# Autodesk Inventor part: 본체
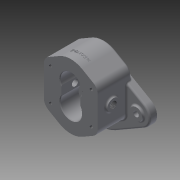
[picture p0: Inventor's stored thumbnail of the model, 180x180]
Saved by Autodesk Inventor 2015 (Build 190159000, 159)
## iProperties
Created: 2025-11
Part Number: 본체
Material: 일반
Document SubType Name: Modeling
Designer: user
Density: 1 g/cm^3
Appearance: 기본값
Author: user
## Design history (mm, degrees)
sketch "스케치1"
  geometry: L1 (74, 17.321)-(26, 45.033); L2 (-74, 17.321)-(-26, 45.033); L3 (74, -17.321)-(26, -45.033); L4 (-26, -45.033)-(-74, -17.321); A1 r 52 centre (0, 0) between (26, 45.033) and (-26, 45.033); A2 r 20 centre (-64, 0) between (-74, -17.321) and (-74, 17.321); A3 r 20 centre (64, 0) between (74, 17.321) and (74, -17.321); 1 further point
  constraints: 8 end point, 8 point on circle, 8 tangent, 3 centre point, 2 horizontal alignment, 1 coincident
  dimensions: "d0" = 104 diameter of A1; "d1" = 40 diameter of A2; "d2" = 40 diameter of A3; "d3" = 64 distance of A2.centre point (0, 0); "d4" = 64 distance of A3.centre point (0, 0)
extrude "돌출1" new body sketch "스케치1" distance "d5" = 12; taper "d6" = 0 deg
sketch "스케치2"
  geometry: L1 (-97.916, 16)-(97.916, 16); L2 (-19, 64.909)-(-45, 49.898); L3 (-45, 49.898)-(-45, -17.898); L4 (-45, -17.898)-(-19, -32.909); L5 (0, 0)-(0, 32); L6 (19, 64.909)-(45, 49.898); L7 (45, 49.898)-(45, -17.898); L8 (45, -17.898)-(19, -32.909); A1 r 52 centre (0, 0) between (-26, -45.033) and (26, -45.033) reference; A2 r 52 centre (0, 0) between (26, 45.033) and (-26, 45.033) reference; A3 r 38 centre (0, 0) between (-19, -32.909) and (19, -32.909); A4 r 38 centre (0, 32) between (-19, 64.909) and (19, 64.909); 1 further point
  constraints: 16 end point, 4 point on circle, 2 centre point, 2 tangent, 2 vertical, 2 vertical alignment, 1 coincident, 1 horizontal, 1 midpoint, 1 parallel, 2 other
  dimensions: "d7" = 76 diameter of A3; "d8" = 16 distance from line of L1 A1.centre; "d9" = 76 diameter of A4; "d10" = 16 distance from line of L1 L5.end; "d11" = 60 deg angle of L4 L2; "d12" = 60 deg angle of L8 L6; "d13" = 45 distance from line of A1.centre L3; "d14" = 90 distance between parallel lines of L3 L7; "d88" = 195.83139 distance of L1.start L1.end
extrude "돌출2" join sketch "스케치2" distance "d15" = 48; taper "d17" = 0 deg; dims "d16" = 8, "d18" = 0
sketch "스케치3"
  geometry: L1 (-16, 0)-(16, 0); L2 (16, 0)-(16, 32); L3 (16, 32)-(-16, 32); L4 (-16, 32)-(-16, 0); C1 r 18 at (0, 32); C2 r 18 at (0, 0); A1 r 38 centre (0, 32) between (19, 64.909) and (-19, 64.909) reference; A2 r 38 centre (0, 0) between (-19, -32.909) and (19, -32.909) reference
  constraints: 8 end point, 2 centre point, 2 coincident, 2 midpoint, 2 parallel, 1 horizontal, 1 perpendicular
  dimensions: "d19" = 36 diameter of C1; "d20" = 36 diameter of C2; "d21" = 16 distance from line of A2.centre L4; "d22" = 32 distance between parallel lines of L2 L4
extrude "돌출3" cut sketch "스케치3" distance "d23" = 31; taper "d24" = 0 deg
sketch "스케치4"
  geometry: L1 (0, 0)-(51.962, 0) reference; L2 (51.962, -48)-(-15.834, -48) reference; L3 (25.817, -48)-(10.31, -48) reference; L4 (18.064, -48)-(18.064, 0); C1 r 10 at (18.064, -25); 1 further point
  constraints: 2 end point, 2 point on line, 1 centre point, 1 midpoint, 1 perpendicular
  dimensions: "d25" = 20 diameter of C1; "d26" = 23 distance from line of L2 C1.centre
extrude "돌출4" join sketch "스케치4" distance "d27" = 3; taper "d28" = 0 deg
sketch "스케치5"
  geometry: C1 r 10 at (0, 0) reference; 1 further point
hole "구멍1" sketch "스케치5" at (0, 0) diameter "d29" = 10.5; stored, may be unused: countersink angle "d35" = 90 deg, drill point angle "d37" = 118 deg; dims "d30" = 11, "d31" = 0.62479, "d32" = 10.589, "d33" = 4, "d34" = 2, "d36" = 17.5
sketch "스케치6"
  geometry: L1 (16, 8.246)-(16, 23.754) reference; L2 (-16, 23.754)-(-16, 8.246) reference; L3 (19, 64.909)-(45, 49.898) reference; L4 (45, 49.898)-(45, 22) reference; L5 (45, 22)-(48, 22) reference; L6 (48, 22)-(48, 10) reference; L7 (48, 10)-(45, 10) reference; L8 (45, 10)-(45, -17.898) reference; L9 (45, -17.898)-(19, -32.909) reference; L10 (-19, -32.909)-(-45, -17.898) reference; L11 (-45, -17.898)-(-45, 10) reference; L12 (-45, 10)-(-48, 10) reference; L13 (-48, 10)-(-48, 22) reference; L14 (-48, 22)-(-45, 22) reference; L15 (-45, 22)-(-45, 49.898) reference; L16 (-45, 49.898)-(-19, 64.909) reference; L17 (-48, 16)-(48, 16); C1 r 11.5 at (0, 32); C2 r 11.5 at (0, 0); A1 r 18 centre (0, 32) between (16, 23.754) and (-16, 23.754) reference; A2 r 18 centre (0, 32) between (16, 23.754) and (-16, 23.754) reference; A3 r 18 centre (0, 0) between (-16, 8.246) and (16, 8.246) reference; A4 r 38 centre (0, 32) between (19, 64.909) and (-19, 64.909) reference; A5 r 38 centre (0, 0) between (-19, -32.909) and (19, -32.909) reference
  constraints: 2 centre point, 2 end point, 2 midpoint, 1 coincident, 1 vertical alignment
  dimensions: "d38" = 23 diameter of C1; "d39" = 23 diameter of C2; "d40" = 16 distance from line of C2.centre L17
extrude "돌출5" cut sketch "스케치6" distance "d41" = 15; taper "d42" = 0 deg
sketch "스케치7"
  geometry: C1 r 25 at (0, 0); A1 r 18 centre (0, 0) between (16, -8.246) and (-16, -8.246) reference
  constraints: 1 centre point, 1 coincident
  dimensions: "d43" = 50 diameter of C1
extrude "돌출6" join sketch "스케치7" distance "d44" = 4; taper "d45" = 0 deg
sketch "스케치8"
  geometry: C1 r 25 at (0, 0) reference; C2 r 15 at (0, 0)
  constraints: 1 centre point, 1 coincident
  dimensions: "d46" = 30 diameter of C2
extrude "돌출7" cut sketch "스케치8" distance "d47" = 7.3; taper "d48" = 0 deg
sketch "스케치9"
  geometry: C1 r 15 at (0, 0) reference; C2 r 10.5 at (0, 0)
  constraints: 1 centre point, 1 coincident
  dimensions: "d49" = 21 diameter of C2
extrude "돌출8" cut sketch "스케치9" stored distance "d50" = 7.3; taper "d51" = 0 deg
sketch "스케치10"
  geometry: C1 r 10 at (-64, 0); C2 r 10 at (64, 0); A1 r 20 centre (-64, 0) between (-74, 17.321) and (-74, -17.321) reference; A2 r 20 centre (64, 0) between (74, -17.321) and (74, 17.321) reference
  constraints: 2 centre point, 2 coincident
  dimensions: "d52" = 20 diameter of C1; "d53" = 20 diameter of C2
extrude "돌출9" join sketch "스케치10" distance "d54" = 3; taper "d55" = 0 deg
sketch "스케치11"
  geometry: L1 (83, 64.909)-(109, 49.898) reference; L2 (109, 49.898)-(109, -17.898) reference; L3 (109, -17.898)-(83, -32.909) reference; L4 (45, -32.909)-(19, -17.898) reference; L5 (19, -17.898)-(19, 49.898) reference; L6 (19, 49.898)-(45, 64.909) reference; C1 r 10 at (0, 0) reference; C2 r 10 at (0, 0) reference; C3 r 10 at (128, 0) reference; C4 r 11.5 at (64, 32) reference; C5 r 11.5 at (64, 0) reference; A1 r 38 centre (64, 32) between (83, 64.909) and (45, 64.909) reference; A2 r 38 centre (64, 0) between (45, -32.909) and (83, -32.909) reference; 1 further point
hole "구멍2" sketch "스케치11" at (0, 0), (128, 0) diameter "d56" = 9; stored, may be unused: countersink angle "d60" = 90 deg, drill point angle "d62" = 118 deg; dims "d57" = 11, "d58" = 4, "d59" = 2, "d61" = 17.5
sketch "스케치12"
  geometry: L1 (-48, 6)-(-48, 26) reference; L2 (-45, 6)-(-45, 26) reference; L3 (48, 6)-(48, 26) reference; L4 (-48, 10.362)-(-48, 21.638) reference; L5 (-48, 16)-(48, 16); L6 (0, 32)-(0, 0); L7 (-34, 43)-(34, 43); L8 (34, 43)-(34, -11); L9 (34, -11)-(-34, -11); L10 (-34, -11)-(-34, 43); A1 r 38 centre (0, 32) between (19, 64.909) and (-19, 64.909) reference; A2 r 38 centre (0, 0) between (-19, -32.909) and (19, -32.909) reference
  constraints: 12 end point, 2 midpoint, 2 parallel, 1 horizontal, 1 perpendicular, 1 vertical
  dimensions: "d63" = 68 distance of L8.end L9.end; "d64" = 54 distance of L7.end L8.end; "d65" = 34 distance between parallel lines of L6 L10; "d66" = 27 distance between parallel lines of L5 L7
hole "구멍3" sketch "스케치12" at (-34, 43), (-34, -11), (34, -11), (34, 43) diameter "d67" = 4.917; stored, may be unused: countersink angle "d71" = 90 deg, drill point angle "d73" = 118 deg; dims "d68" = 12, "d69" = 4, "d70" = 2, "d72" = 14
fillet "모깎기1" dims "d74" = 15
fillet "모깎기2" dims "d75" = 3
fillet "모깎기3" dims "d76" = 3
chamfer "모따기1" distance "d77" = 1; stored, may be unused: second distance "d78" = 2, angle "d79" = 45 deg
fillet "모깎기4" dims "d80" = 0.3
chamfer "모따기2" distance "d81" = 0.7; stored, may be unused: second distance "d82" = 2, angle "d83" = 30 deg
node "작업 평면1"
sketch "스케치13"
  geometry: L1 (37.5, -48)-(19, -48) reference; 2 further points
  constraints: 1 vertical alignment, 1 other
  dimensions: "d84" = 16 distance from line of L1 point (0, -32)
feature "엠보싱1" sketch "스케치13" dims "d0" = 104, "d1" = 40, "d2" = 40, "d3" = 64, "d4" = 64, "d85" = 0.5, "d86" = 0
node "솔리드1"
mirror "대칭1"
mirror "대칭2"
node "투영된 루프1"
node "절단 모서리 투영1"
node "절단 모서리 투영2"
